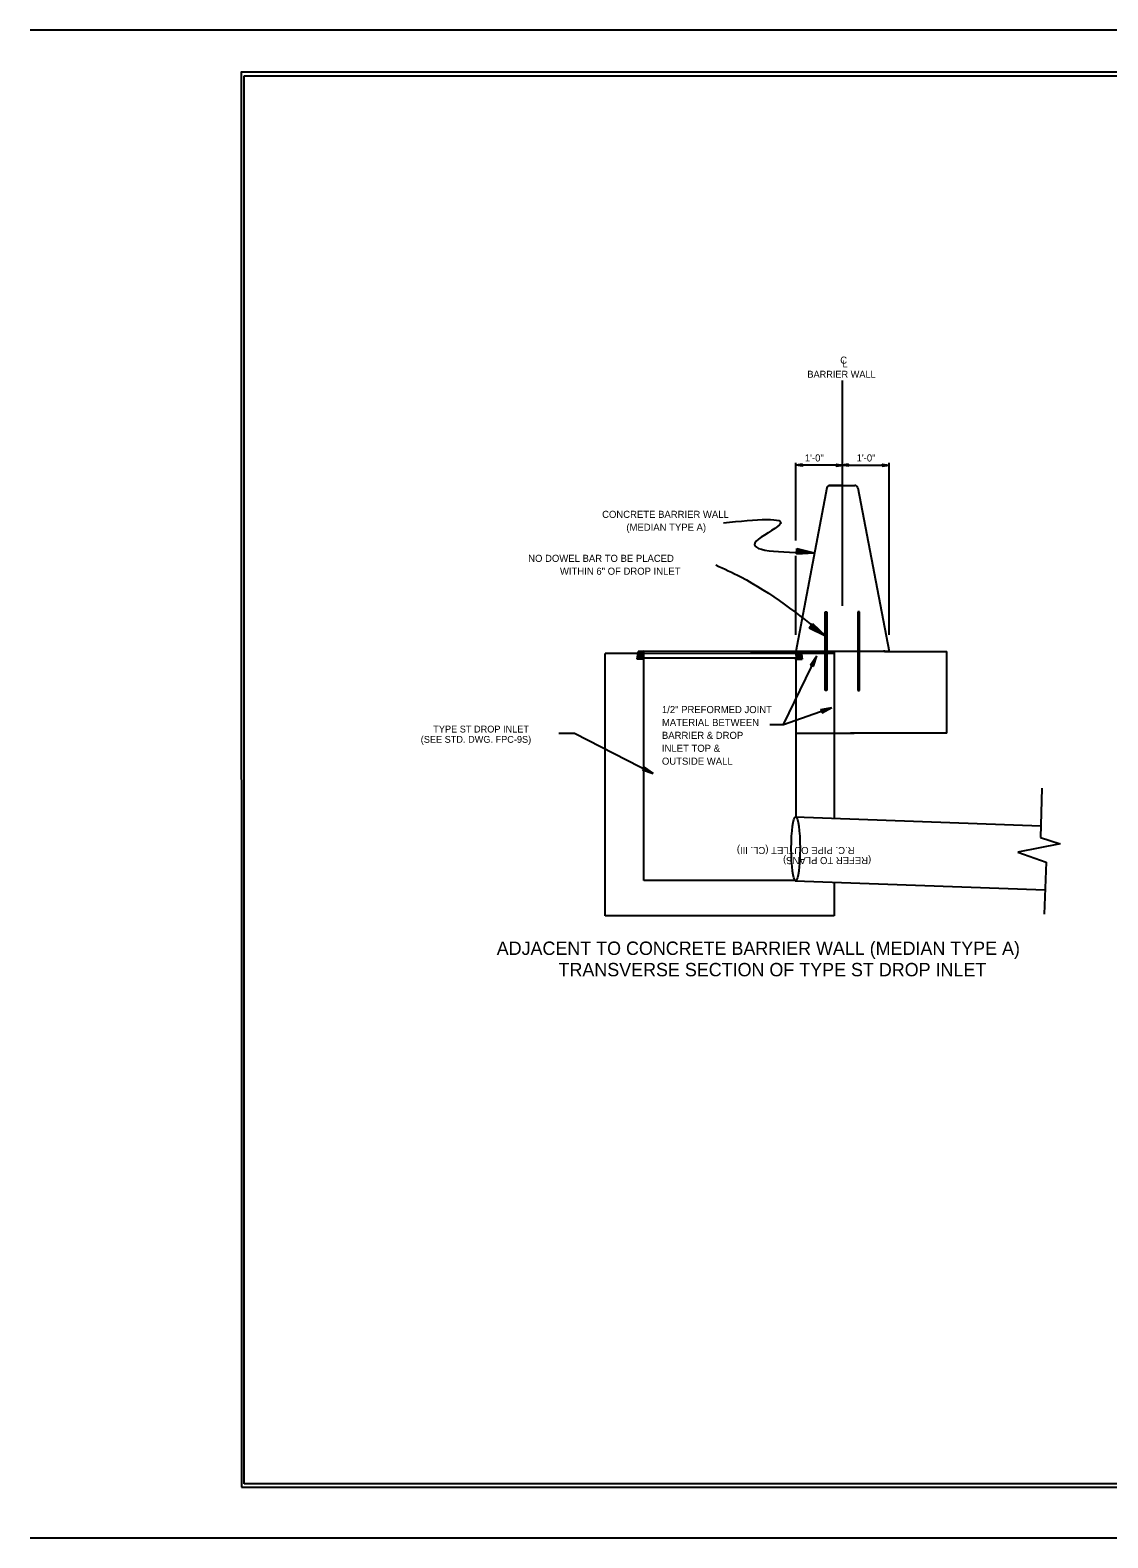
# Model space of a CAD drawing. Extents: x 714919 to 718439, y 1619644 to 1621844.
# Drawn here: x 714919 to 716492, y 1619644 to 1621844 of the extents above; entities that cross this region are included whole.
import ezdxf

# ---------------------------------------------------------------- set-up
doc = ezdxf.new("R2010")
doc.units = 0
for name, color, linetype in [('R_Annotation', 7, 'Continuous'), ('R_Border', 7, 'Continuous'), ('R_Centerline', 7, 'Continuous'), ('R_Dimension', 7, 'Continuous'), ('R_No Plot', 7, 'Continuous'), ('T_Drafting', 7, 'Continuous')]:
    doc.layers.add(name, color=color, linetype=linetype)

msp = doc.modelspace()

# ---------------------------------------------------------------- linework, layer by layer
at = {"layer": 'R_Annotation'}
for p, q in [((716037.2, 1621079.5), (716038, 1621087.3)), ((716037.2, 1621079.5), (716063.4, 1621080.9)), ((716037.3, 1621080.1), (716059.1, 1621081.3)), ((716037.4, 1621081.5), (716050.4, 1621082.2)), ((716037.4, 1621080.8), (716054.7, 1621081.8)), ((716037.5, 1621082.1), (716046, 1621082.5)), ((716037.6, 1621082.8), (716041.7, 1621083)), ((716037.7, 1621084.6), (716046, 1621082.5)), ((716037.7, 1621084), (716041.7, 1621083)), ((716037.8, 1621086), (716054.7, 1621081.8)), ((716037.8, 1621085.3), (716050.4, 1621082.2)), ((716037.9, 1621086.6), (716059.1, 1621081.3)), ((716038, 1621087.3), (716063.4, 1621080.9)), ((716056.1, 1620971.6), (716060.6, 1620978)), ((716056.1, 1620971.6), (716079.6, 1620960)), ((716056.5, 1620972.1), (716076.1, 1620962.4)), ((716056.9, 1620972.6), (716072.5, 1620965)), ((716057.3, 1620973.1), (716068.9, 1620967.4)), ((716057.7, 1620973.8), (716065.3, 1620970)), ((716058, 1620974.3), (716061.8, 1620972.5)), ((716058.7, 1620975.2), (716061.8, 1620972.5)), ((716059.1, 1620975.8), (716065.3, 1620970)), ((716059.5, 1620976.3), (716068.9, 1620967.4)), ((716059.9, 1620976.9), (716072.5, 1620965)), ((716060.2, 1620977.4), (716076.1, 1620962.4)), ((716060.6, 1620978), (716079.6, 1620960)), ((716018.6, 1620830.6), (716067, 1620930.8)), ((716057.8, 1620917.5), (716067, 1620930.8)), ((716058.2, 1620917.3), (716065.8, 1620928.4)), ((716058.6, 1620917.1), (716064.6, 1620926)), ((716058.9, 1620917), (716063.4, 1620923.6)), ((716059.3, 1620916.8), (716062.3, 1620921.1)), ((716059.7, 1620916.6), (716061.1, 1620918.7)), ((716060.4, 1620916.3), (716061.1, 1620918.7)), ((716060.7, 1620916.1), (716062.3, 1620921.1)), ((716061.1, 1620915.9), (716063.4, 1620923.6)), ((716061.4, 1620915.7), (716064.6, 1620926)), ((716061.8, 1620915.6), (716065.8, 1620928.4)), ((716062.2, 1620915.4), (716067, 1620930.8)), ((716057.8, 1620917.5), (716062.2, 1620915.4)), ((716018.6, 1620830.6), (716088.9, 1620855.2)), ((716073, 1620852.2), (716088.9, 1620855.2)), ((716073, 1620852.2), (716074.6, 1620847.6)), ((716073.2, 1620851.8), (716086.4, 1620854.3)), ((716073.3, 1620851.4), (716083.8, 1620853.4)), ((716073.4, 1620851), (716081.3, 1620852.5)), ((716074.2, 1620848.8), (716081.3, 1620852.5)), ((716074.4, 1620848.4), (716083.8, 1620853.4)), ((716074.5, 1620848), (716086.4, 1620854.3)), ((716074.6, 1620847.6), (716088.9, 1620855.2)), ((715998.4, 1620830.6), (716018.6, 1620830.6)), ((716073.6, 1620850.6), (716078.7, 1620851.6)), ((716073.7, 1620850.3), (716076.2, 1620850.7)), ((716074, 1620849.5), (716076.2, 1620850.7)), ((716074.1, 1620849.2), (716078.7, 1620851.6)), ((715690.7, 1620817.9), (715713.4, 1620817.9)), ((715713.4, 1620817.9), (715828.1, 1620758.9)), ((715814.9, 1620768.4), (715812.7, 1620764.1)), ((715812.7, 1620764.1), (715828.1, 1620758.9)), ((715812.9, 1620764.5), (715825.7, 1620760.1)), ((715813.1, 1620764.8), (715823.2, 1620761.4)), ((715813.3, 1620765.2), (715820.9, 1620762.6)), ((715813.5, 1620765.5), (715818.5, 1620763.9)), ((715813.7, 1620765.9), (715816.1, 1620765.1)), ((715814, 1620766.6), (715816.1, 1620765.1)), ((715814.2, 1620766.9), (715818.5, 1620763.9)), ((715814.4, 1620767.3), (715820.9, 1620762.6)), ((715814.6, 1620767.6), (715823.2, 1620761.4)), ((715814.8, 1620768), (715825.7, 1620760.1)), ((715814.9, 1620768.4), (715828.1, 1620758.9)), ((715814.5, 1620710.1), (715814.5, 1620711.7))]:
    msp.add_line(p, q, dxfattribs=at)
for points in [[(715931, 1621125), (716012.6, 1621121.7), (715978.6, 1621097.9), (716063.4, 1621080.9)], [(715919.6, 1621063.3), (715955.9, 1621045.9), (716079.7, 1620960)]]:
    msp.add_spline(points, degree=3, dxfattribs=at)
at = {"layer": 'R_Border'}
for p, q in [((718439, 1621843.8), (714919, 1621843.5)), ((715231.2, 1619722.5), (715231.3, 1621777.1)), ((715231.3, 1621777.1), (718393.1, 1621777.1)), ((718393.2, 1619722.5), (715231.2, 1619722.5)), ((714919.1, 1619643.5), (718439.3, 1619643.8))]:
    msp.add_line(p, q, dxfattribs=at)
at = {"layer": 'R_Centerline'}
msp.add_line((716104.6, 1621003.7), (716104.6, 1621332.3), dxfattribs=at)
at = {"layer": 'R_Dimension'}
for p, q in [((716036.2, 1621099.2), (716036.2, 1621212.5)), ((716046.3, 1621210.5), (716036.2, 1621209)), ((716105.3, 1621209), (716036.2, 1621209)), ((716046.3, 1621207.5), (716036.2, 1621209)), ((716046.3, 1621210.2), (716037.8, 1621209)), ((716046.3, 1621207.7), (716037.8, 1621209)), ((716046.3, 1621210), (716039.6, 1621209)), ((716046.3, 1621208), (716039.6, 1621209)), ((716046.3, 1621209.7), (716041.3, 1621209)), ((716046.3, 1621208.2), (716041.3, 1621209)), ((716046.3, 1621209.5), (716043, 1621209)), ((716046.3, 1621208.5), (716043, 1621209)), ((716046.3, 1621209.2), (716044.7, 1621209)), ((716046.3, 1621208.8), (716044.7, 1621209)), ((716046.3, 1621210.5), (716046.3, 1621207.5)), ((716095.1, 1621210.5), (716105.3, 1621209)), ((716095.1, 1621207.5), (716095.1, 1621210.5)), ((716095.1, 1621210.2), (716103.6, 1621209)), ((716095.1, 1621210), (716101.9, 1621209)), ((716095.1, 1621209.7), (716100.1, 1621209)), ((716095.1, 1621209.5), (716098.5, 1621209)), ((716095.1, 1621209.2), (716096.8, 1621209)), ((716095.1, 1621207.5), (716105.3, 1621209)), ((716095.1, 1621208.5), (716098.5, 1621209)), ((716095.1, 1621208), (716101.9, 1621209)), ((716095.1, 1621207.7), (716103.6, 1621209)), ((716095.1, 1621208.2), (716100.1, 1621209)), ((716095.1, 1621208.8), (716096.8, 1621209)), ((716113.5, 1621210.5), (716103.3, 1621209)), ((716103.3, 1621209), (716172.4, 1621209)), ((716113.5, 1621207.5), (716103.3, 1621209)), ((716113.5, 1621210.2), (716105, 1621209)), ((716113.5, 1621207.7), (716105, 1621209)), ((716113.5, 1621210), (716106.7, 1621209)), ((716113.5, 1621208), (716106.7, 1621209)), ((716113.5, 1621209.7), (716108.5, 1621209)), ((716113.5, 1621208.2), (716108.5, 1621209)), ((716113.5, 1621209.5), (716110.1, 1621209)), ((716113.5, 1621208.5), (716110.1, 1621209)), ((716113.5, 1621209.2), (716111.8, 1621209)), ((716113.5, 1621208.8), (716111.8, 1621209)), ((716113.5, 1621207.5), (716113.5, 1621210.5)), ((716162.3, 1621210.5), (716172.4, 1621209)), ((716162.3, 1621210.5), (716162.3, 1621207.5)), ((716162.3, 1621210.2), (716170.8, 1621209)), ((716162.3, 1621210), (716169, 1621209)), ((716162.3, 1621209.7), (716167.3, 1621209)), ((716162.3, 1621209.5), (716165.6, 1621209)), ((716162.3, 1621209.2), (716163.9, 1621209)), ((716162.3, 1621207.5), (716172.4, 1621209)), ((716162.3, 1621208.5), (716165.6, 1621209)), ((716162.3, 1621208), (716169, 1621209)), ((716162.3, 1621207.7), (716170.8, 1621209)), ((716162.3, 1621208.2), (716167.3, 1621209)), ((716162.3, 1621208.8), (716163.9, 1621209)), ((716172.4, 1621099.2), (716172.4, 1621212.5)), ((716172.4, 1620961.5), (716172.4, 1621099.2)), ((716036.2, 1620961.5), (716036.2, 1621076.7)), ((716036.2, 1620972.8), (716036.2, 1621070.3)), ((716172.4, 1620972.8), (716172.4, 1621070.3))]:
    msp.add_line(p, q, dxfattribs=at)
at = {"layer": 'R_No Plot'}
msp.add_lwpolyline([(715227.2, 1619717.3), (718397.1, 1619717.4), (718397.2, 1621782.5), (715227.1, 1621782.3)], close=True, dxfattribs=at)
at = {"layer": 'T_Drafting'}
for p, q in [((716081.7, 1621176), (716036.2, 1620937.2)), ((716084.4, 1621179.2), (716122.7, 1621179.2)), ((716105.3, 1621179.2), (716085.9, 1621179.2)), ((716126.9, 1621176), (716172.4, 1620937.2)), ((716079.2, 1620879.9), (716079.2, 1620994.8)), ((716079.2, 1620994.8), (716081.8, 1620994.8)), ((716081.8, 1620994.8), (716081.8, 1620879.9)), ((716129.4, 1620994.8), (716126.8, 1620994.8)), ((716126.8, 1620994.8), (716126.8, 1620879.9)), ((716129.4, 1620879.9), (716129.4, 1620994.8)), ((715788, 1620934.1), (715758.2, 1620934.1)), ((715758.2, 1620606.1), (715758.2, 1620934.1)), ((716036.6, 1620934.1), (715788, 1620934.1)), ((715806.3, 1620937.2), (715804.5, 1620925.7)), ((715814.5, 1620925.7), (715804.5, 1620925.7)), ((715804.8, 1620927.3), (715807.8, 1620930.3)), ((715805.2, 1620930.2), (715807.8, 1620932.9)), ((715805.7, 1620933.2), (715807.8, 1620935.4)), ((715805.8, 1620925.7), (715808, 1620927.9)), ((715806.1, 1620936.1), (715807.2, 1620937.2)), ((715807.8, 1620937.2), (715806.3, 1620937.2)), ((715807.8, 1620927.9), (715807.8, 1620937.2)), ((715814.5, 1620927.9), (715807.8, 1620927.9)), ((715808, 1620937.3), (715814.3, 1620937.3)), ((715808, 1620928), (715808, 1620937.3)), ((715813, 1620929.9), (715808, 1620935)), ((715812.3, 1620928), (715808, 1620932.3)), ((715809.6, 1620928), (715808, 1620929.6)), ((715808, 1620928), (715812.5, 1620928)), ((715813.6, 1620932), (715808.3, 1620937.3)), ((715808.4, 1620925.7), (715810.5, 1620927.9)), ((715810.9, 1620925.7), (715813.1, 1620927.9)), ((715814.1, 1620934.2), (715811, 1620937.3)), ((715812.5, 1620928), (715814.8, 1620936.8)), ((715813.4, 1620925.7), (715814.5, 1620926.8)), ((715814.7, 1620936.3), (715813.6, 1620937.3)), ((716036.2, 1620937.2), (715814.3, 1620937.3)), ((715814.5, 1620603), (715814.5, 1620934.1)), ((715814.5, 1620925.7), (715814.5, 1620927.9)), ((715814.5, 1620927.9), (716042.4, 1620927.9)), ((716034.6, 1620937.2), (715970.3, 1620937.2)), ((716079.2, 1620937.2), (716034.6, 1620937.2)), ((716038, 1620927.9), (716035.7, 1620936.7)), ((716035.8, 1620936.2), (716036.9, 1620937.2)), ((716035.9, 1620925.7), (716035.9, 1620927.9)), ((716035.9, 1620927.9), (716042.5, 1620927.9)), ((716036.9, 1620925.7), (716035.9, 1620926.8)), ((716035.9, 1620925.7), (716045.8, 1620925.7)), ((716042.8, 1620937.2), (716036.2, 1620937.2)), ((716036.2, 1620925.7), (716036.2, 1620924.2)), ((716036.2, 1620924.2), (716036.2, 1620695.6)), ((716036.4, 1620934.1), (716039.5, 1620937.2)), ((716092.4, 1620934.1), (716036.6, 1620934.1)), ((716037, 1620931.9), (716042.2, 1620937.2)), ((716039.4, 1620925.7), (716037.3, 1620927.9)), ((716037.5, 1620929.9), (716042.5, 1620934.9)), ((716038.2, 1620927.9), (716042.5, 1620932.2)), ((716042, 1620925.7), (716039.8, 1620927.9)), ((716040.9, 1620927.9), (716042.5, 1620929.6)), ((716042.4, 1620927.9), (716042.8, 1620937.2)), ((716042.5, 1620927.9), (716042.5, 1620937.3)), ((716042.5, 1620937.3), (716044.1, 1620937.3)), ((716045.5, 1620927.3), (716042.5, 1620930.3)), ((716044.5, 1620925.7), (716042.5, 1620927.8)), ((716045.2, 1620930.2), (716042.7, 1620932.7)), ((716044.7, 1620933.2), (716042.8, 1620935.1)), ((716044.3, 1620936.2), (716043.2, 1620937.3)), ((716044.1, 1620937.3), (716045.8, 1620925.7)), ((716092.4, 1620934.1), (716044.6, 1620934.1)), ((716126.8, 1620937.2), (716081.8, 1620937.2)), ((716092.4, 1620936.2), (716092.4, 1620693.6)), ((716092.4, 1620934.1), (716092.4, 1620818)), ((716172.4, 1620937.2), (716129.4, 1620937.2)), ((716166.1, 1620937.3), (716164.5, 1620937.3)), ((716165.8, 1620937.2), (716172.4, 1620937.2)), ((716172.4, 1620937.2), (716256.9, 1620937.2)), ((716256.9, 1620818), (716256.9, 1620937.2)), ((716081.8, 1620879.9), (716079.2, 1620879.9)), ((716126.8, 1620879.9), (716129.4, 1620879.9)), ((716036.2, 1620818), (716121.5, 1620818)), ((716256.9, 1620818), (716116.2, 1620818)), ((716395.5, 1620737.5), (716393.3, 1620665.8)), ((716035.6, 1620695.6), (716393.8, 1620682.8)), ((716422.2, 1620656.2), (716360.2, 1620644.4)), ((716393.3, 1620665.8), (716422.2, 1620656.2)), ((716360.2, 1620644.4), (716401.9, 1620629.4)), ((716401.9, 1620629.4), (716398.7, 1620553.5)), ((715758.2, 1620551.2), (715758.2, 1620606.1)), ((716036.2, 1620603), (715814.5, 1620603)), ((716035.6, 1620602.4), (716400.2, 1620589.4)), ((716092.4, 1620598.9), (716092.4, 1620551.2)), ((716092.4, 1620551.2), (715758.2, 1620551.2))]:
    msp.add_line(p, q, dxfattribs=at)
for centre, radius, start, end in [((716085.6, 1621175.4), 3.86, 84.9683, 170.2842), ((716123, 1621175.4), 3.86, 9.7158, 95.0317), ((715807.9, 1620927.8), 0.452, 0, 90), ((715814.4, 1620936.8), 0.47, 348.6901, 90), ((716036.1, 1620936.7), 0.47, 90, 191.3099), ((716042.5, 1620927.8), 0.452, 90, 180)]:
    msp.add_arc(centre, radius, start, end, dxfattribs=at)
msp.add_ellipse((716036.2, 1620649.3), major_axis=(0, -46.3), ratio=0.137917, dxfattribs=at)

# ---------------------------------------------------------------- texts
at = {"layer": 'R_Annotation'}
for s, height, p in [('CONCRETE BARRIER WALL', 10.368, (715753.7, 1621132)), ('(MEDIAN TYPE A)', 10.368, (715789.1, 1621113.2)), ('NO DOWEL BAR TO BE PLACED', 10.368, (715645.8, 1621067.8)), ('WITHIN 6" OF DROP INLET', 10.368, (715692.2, 1621049)), ('1/2" PREFORMED JOINT', 10.368, (715841, 1620847.1)), ('MATERIAL BETWEEN', 10.368, (715841, 1620828.3)), ('(SEE STD. DWG. FPC-9S)', 10, (715489, 1620803.8)), ('TYPE ST DROP INLET', 10, (715507.3, 1620818.8)), ('BARRIER & DROP', 10.368, (715841, 1620809.5)), ('INLET TOP &', 10.368, (715841, 1620790.6)), ('OUTSIDE WALL', 10.368, (715841, 1620771.8)), ('ADJACENT TO CONCRETE BARRIER WALL (MEDIAN TYPE A) ', 19.537, (715599.9, 1620494.2)), ('TRANSVERSE SECTION OF TYPE ST DROP INLET', 19.537, (715690.1, 1620463))]:
    msp.add_text(s, height=height, dxfattribs=at).set_placement(p)
for s, p in [('R.C. PIPE OUTLET (CL. III) ', (716122.1, 1620651.8)), ('(REFER TO PLANS)', (716146.4, 1620637.1))]:
    msp.add_text(s, height=10.368, rotation=180, dxfattribs=at).set_placement(p)
at = {"layer": 'R_Centerline'}
for s, height, p in [('C', 10.4, (716101.2, 1621357)), ('L', 10.4, (716104.4, 1621351.6)), ('BARRIER WALL', 10, (716053.3, 1621336.7))]:
    msp.add_text(s, height=height, dxfattribs=at).set_placement(p)
at = {"layer": 'R_Dimension'}
for p in [(716049.6, 1621214.3), (716125.1, 1621214.3)]:
    msp.add_text('1\'-0"', height=10.37, dxfattribs=at).set_placement(p)

doc.saveas('drawing.dxf')
